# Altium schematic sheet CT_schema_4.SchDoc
size 283 x 147 mm
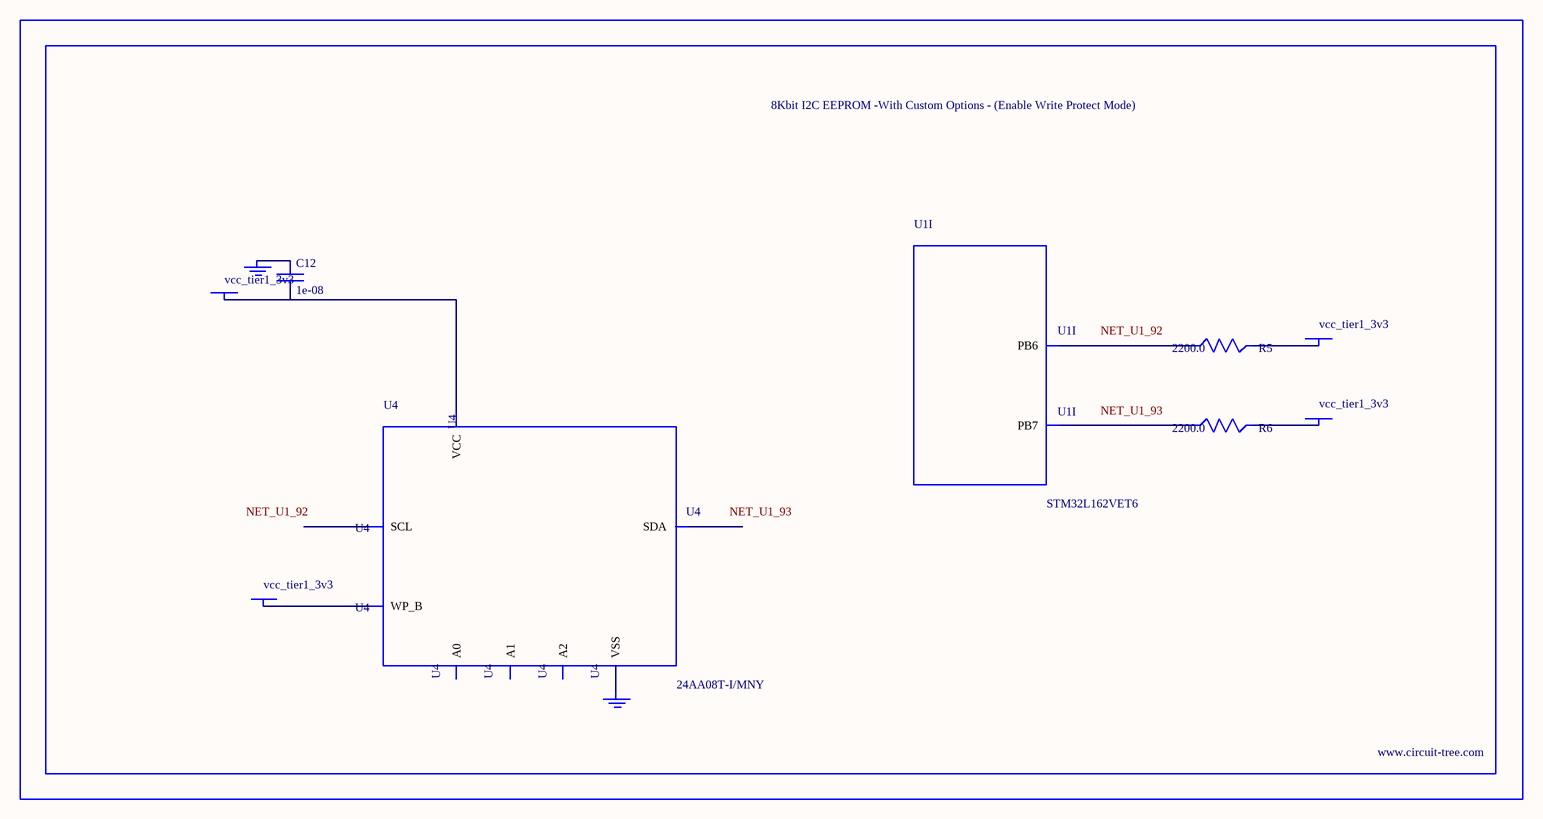
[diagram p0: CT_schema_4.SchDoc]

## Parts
BORDER3  (no value)
C12  1e-08  [C0402]
GND_INSTANCE_3_0  (no value)
GND_INSTANCE_3_1  (no value)
POWER_INSTANCE_3_0  vcc_tier1_3v3
POWER_INSTANCE_3_1  vcc_tier1_3v3
POWER_INSTANCE_3_2  vcc_tier1_3v3
POWER_INSTANCE_3_3  vcc_tier1_3v3
R5  2200.0  [R0603]
R6  2200.0  [R0603]
U1  STM32L162VET6  [LQFP100]  (part I of 10)
U4  24AA08T-I/MNY  [TDFN-8/6MM]

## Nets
NetC12_1: C12.1 GND_INSTANCE_3_0.0(GND)
NetC12_2: C12.2 POWER_INSTANCE_3_1.0(PWR) U4.8(VCC)
NetGND_INSTANCE_3_1_0: GND_INSTANCE_3_1.0(GND) U4.4(VSS)
NetPOWER_INSTANCE_3_0_0: POWER_INSTANCE_3_0.0(PWR) U4.7(WP_B)
NetPOWER_INSTANCE_3_2_0: POWER_INSTANCE_3_2.0(PWR) R5.2
NetPOWER_INSTANCE_3_3_0: POWER_INSTANCE_3_3.0(PWR) R6.2
NetR5_1: R5.1 U1.92(PB6)
NetR6_1: R6.1 U1.93(PB7)

Not connected (* = marked no-connect by the designer): U4 1(A0) 2(A1) 3(A2) 5(SDA) 6(SCL)

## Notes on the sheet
- Labels drawn without touching a wire or pin: NET_U1_92, NET_U1_93

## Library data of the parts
BORDER3 = BORDER_PAGE3
C12 = C0402C103K3RAC
GND_INSTANCE_3_0 GND_INSTANCE_3_1 = GND
POWER_INSTANCE_3_0-POWER_INSTANCE_3_3 = PWR
R5 R6 = RC0603JR-072K2L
